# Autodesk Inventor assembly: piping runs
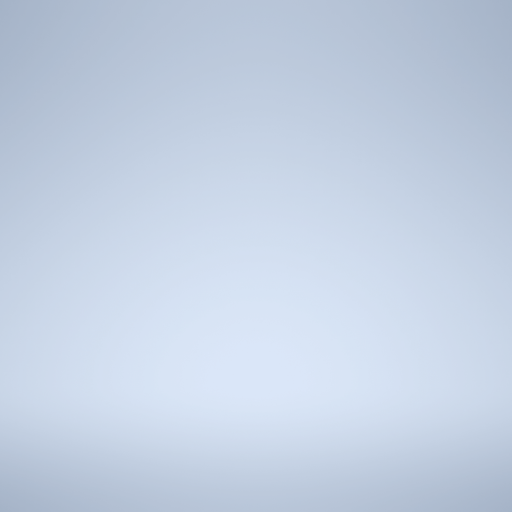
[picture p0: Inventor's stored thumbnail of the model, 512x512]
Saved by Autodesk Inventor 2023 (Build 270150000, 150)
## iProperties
ActiveState: False
Angle: UnInitValue
BendRadius: 12.700 mm
CouplingKey: UnInitValue
DefaultBendRadius: UnInitValue
Diameter: 1/2
DiameterType: Nominal
Elbow45Key: UnInitValue
Elbow90Key: UnInitValue
ElbowCustomKey: UnInitValue
Ending: UnInitValue
FittingMaterial: UnInitValue
FittingStandard: UnInitValue
FlangeKey: UnInitValue
Gap: UnInitValue
GasketKey: UnInitValue
ID: 12.700 mm
IsButtWelded: UnInitValue
IsFlanged: UnInitValue
IsSelfDraining: UnInitValue
Material: UnInitValue
MixedUnits: UnInitValue
Name: Przewód hydrauliczny – bez złączek
OD: 22.352 mm
PipeKey: v3#d489867e-ac9b-47ea-b952-0a1b885f66be#4
PipeType: Flexible Hose
PipingComponentColor: Jak materiał
RoundUpValue: 3.175 mm
RouteDirection45: UnInitValue
RouteDirection90: UnInitValue
Schedule: ID=0.5
ShowGap: UnInitValue
Standard: UnInitValue
SuppressEndFitting: True
SuppressStartFitting: True
UseFlangsForCouplings: UnInitValue
UseSubASM: True
_ComponentInfo: <CS><C N="Pipe" R="1.117600" OR="1.117600" IR="0.635000" PL="PL" PartType="" SymKey="" PN="Parker Hydraulic Hose - No Skive 1/2"><CO N="1"><FE V="0"/><FD V="0"/
BendRadius: UnInitValue
CategoryName: UnInitValue
CouplingKey: v3#12b64993-10e6-4915-8315-0c0cce209ad0#8
Diameter: M40
Elbow45Key: v3#28e76e79-e22c-40ab-8be2-ff545b1407c5#8
Elbow90Key: v3#1f65ece3-c41a-48d4-8661-909ed34ade86#8
EndFittingKey: UnInitValue
IntermediateSegmentsInc: 1.000 mm
IntermediateSegmentsMax: 5000.000 mm
IntermediateSegmentsMin: 60.000 mm
Name: JIS G 3458/JIS B 2316 - Rury stalowe spawane i łączniki
PipeKey: v3#da14b0ab-0b36-4851-8d66-8c9cd0bcbe86#23
PipeType: Rigid Pipe
RoundUpValue: UnInitValue
RouteDirection45: True
RouteDirection90: True
Schedule: 80
StartFittingKey: UnInitValue
SuppressEndFitting: UnInitValue
SuppressStartFitting: UnInitValue
TerminationSegmentsInc: 1.000 mm
TerminationSegmentsMax: 5000.000 mm
TerminationSegmentsMin: 60.000 mm
UseSubASM: UnInitValue
_ComponentInfo: <CS><C N="Pipe" R="2.430000" IR="1.920000" PL="PL" PN="JIS G 3458 Pipe 40 A x Sch 80"><CO N="1"><FE V="0"/><FD V="1"/><ET V="Welded"/><NS  V="M40"/><MA V="0.000
CouplingKey: v3#ed415c76-4cec-44a3-ba67-72e47bf70384#4
Elbow45Key: v3#2e5fd082-3851-4eb0-bde1-6c7078a7d72b#4
Elbow90Key: v3#82a08401-12d7-413b-b7f9-9cf3b607be7b#4
IntermediateSegmentsInc: 2.540 mm
IntermediateSegmentsMax: 5080.000 mm
IntermediateSegmentsMin: 25.400 mm
Name: ASTM A53/A53M-ASME B16.11 - Rury stalowe spawane
PipeKey: v3#4ce5e9fa-6da0-4801-ac02-ee7a0fb518d6#7
Schedule: 40
TerminationSegmentsInc: 2.540 mm
TerminationSegmentsMax: 5080.000 mm
TerminationSegmentsMin: 25.400 mm
_ComponentInfo: <CS><C N="Pipe" R="1.066800" IR="0.789940" PL="PL" PN="ASTM A 53/A 53M Pipe 1/2 - Schedule 40"><CO N="1"><FE V="0"/><FD V="0"/><ET V="Welded"/><NS  V="1/2"/><MA
CouplingKey: v3#7e56b2cb-a132-4546-b8a7-a14538454b94#3
Elbow45Key: v3#a96c5204-26e4-4bb2-b8f1-f0623fbc94bb#2
Elbow90Key: v3#b72bb08b-ad33-47cc-a03d-7f3d76c6616b#3
ID: UnInitValue
IntermediateSegmentsMin: 50.800 mm
IsButtWelded: False
IsFlanged: False
IsSelfDraining: False
MixedUnits: False
Name: ISO 7598/ISO 49 - Rury stalowe gwintowane ze stalowymi łącznikami
OD: UnInitValue
PipeKey: v3#1052637f-74b5-47f4-adeb-d4e8d3fa53b8#1
Schedule: ID=16.1
TerminationSegmentsMin: 50.800 mm
_ComponentInfo: <CS><C N="Pipe" R="1.065000" IR="0.805000" PL="PL" PN="ISO 7598 Tube with Threaded Ends DN15"><CO N="1"><FE V="0"/><FD V="1"/><ET V="Threaded"/><NS V="1/2"/><MA
EndFittingKey: v3#c5e461f5-5e73-4f2e-8c1e-4358d4d6f46c#4
Name: Przewód hydrauliczny – gwint wewnętrzny - obrotowy
StartFittingKey: v3#c5e461f5-5e73-4f2e-8c1e-4358d4d6f46c#4
SuppressEndFitting: False
SuppressStartFitting: False
Diameter: 6
Elbow90Key: v3#97ecdcaf-8aa3-4fb0-8b6a-3da783de2ad5#108
Gap: 1.575 mm
IntermediateSegmentsInc: 0.000 mm
IntermediateSegmentsMin: 76.200 mm
IsButtWelded: True
Name: ASTM A 53/A-ASME B16.9 - Rura stalowa ze szwem
PipeKey: v3#4ce5e9fa-6da0-4801-ac02-ee7a0fb518d6#77
RouteDirection45: False
ShowGap: True
TerminationSegmentsInc: 0.000 mm
TerminationSegmentsMin: 76.200 mm
_ComponentInfo: <CS><C N="Elbow90" ER="15.240000" S1="15.240000" S2="15.240000" D1="0.000000" D2="0.000000" PartType="fitting" SymKey="ELBW"><CO N="1"><FE V="2"/><FD V="0"/><ET
CouplingKey: v3#181262db-c004-4877-bc40-c64b931a44f6#3
Elbow45Key: v3#960407aa-00b9-4d72-aae7-d50595845cfd#3
Elbow90Key: v3#6c92b367-65e9-486b-b952-db434ae2548d#3
IntermediateSegmentsMin: 20.000 mm
Name: JIS G 3442/JIS B 2301  Rury stalowe gwintowane ze stalowymi łącznikami
PipeKey: v3#9964fba4-9d5a-4d75-85a8-e38022ccdce1#2
TerminationSegmentsMin: 20.000 mm
_ComponentInfo: <CS><C N="Pipe" R="1.085000" IR="0.805000" PL="PL" PN="JIS G 3442 Pipe with Threaded Ends 21.7 x 2.8"><CO N="1"><FE V="0"/><FD V="1"/><ET V="Threaded"/><NS V="1
CouplingKey: v3#771d4942-b9e7-43bc-9d41-ab12a9580492#3
Elbow45Key: v3#626cc28c-1a24-4045-be0d-40d896dc828d#3
Elbow90Key: v3#bc6b44ab-9235-4590-b699-74498030a1ff#3
Name: ANSI/ASME B36.19M-ASME B16.3 - Rury gwintowane ze stalowymi łącznikami
PipeKey: v3#323c0148-c750-449d-a0c6-11721f2a5046#1
Schedule: 40S
_ComponentInfo: <CS><C N="Pipe" R="1.066800" IR="0.789940" PL="PL" PN="ANSI/ASME B36.19M Pipe with Threaded Ends 1/2 - Schedule 40S"><CO N="1"><FE V="0"/><FD  V="1"/><ET V="Thr
Elbow45Key: v3#97879d80-057e-491b-840b-74a9b3a7cf63#17
Elbow90Key: v3#ace818b0-7b7c-4ad9-b19c-6da358a202c1#17
Name: DIN 2458/DIN 2605 - Rury stalowe spawane i łączniki
PipeKey: v3#dcef2839-8903-4c98-a96c-b861f5d9bb7f#98
Schedule: ID=30.7
_ComponentInfo: <CS><C N="Pipe" R="2.415000" IR="1.535000" PL="PL" PN="DIN 2458 Pipe 48.3 x 8.8"><CO N="1"><FE V="2"/><FD V="0"/><ET V="Welded"/><NS V="M40"/><MA  V="0.000000"/
EndFittingKey: v3#c8250148-a7b6-458b-b7bd-3b56763ca7cc#13
Name: Przewód hydrauliczny – gwint stożkowy zewnętrzny
StartFittingKey: v3#c8250148-a7b6-458b-b7bd-3b56763ca7cc#13
Elbow90Key: v3#6a678020-d9d9-4685-bba9-906b9a167083#10
FlangeKey: v3#c11442d2-c568-438f-a870-8ac9b5b636cb#10
GasketKey: v3#2a41914c-f5fb-4682-9c6a-1870d826d3d0#23
IsFlanged: True
Name: ASTM A 53/A-ASME B16.5 - Rura stalowa gwintowana kołnierzowa
PipeKey: v3#c5bd7d28-cdb3-4507-9f3d-c2787d93fe8a#40
_ComponentInfo: <CS><C N="Elbow90" ER="21.590000" S1="21.590000" S2="21.590000" D1="0.000000" D2="0.000000" PartType="fitting" SymKey="ELFL"><CO N="1"><FE V="2"/><FD V="1"/><ET
CouplingKey: v3#d2599e7a-1865-48da-a234-5418a1cd5dfe#3
Elbow45Key: v3#6ce5b1be-37aa-4928-b23a-0df64e6ddf38#2
Elbow90Key: v3#9fba244e-81ed-4fc6-a9ac-7eb372fa3ffe#3
Name: DIN 2458/DIN EN 10242 - Rury stalowe gwintowane i stalowe łączniki
PipeKey: v3#d689fd5f-ac5a-46d7-a883-3089b2f6e0a4#28
Schedule: ID=12.3
_ComponentInfo: <CS><C N="Pipe" R="1.065000" IR="0.615000" PL="PL" PN="DIN 2458 Pipe with Threaded Ends 21.3 x 4.5"><CO N="1"><FE V="0"/><FD V="1"/><ET V="Threaded"/><NS V="1/2
CouplingKey: v3#b06656e5-2b55-488c-bcf0-6a90c79c4683#2
Elbow45Key: v3#421a8b99-1721-409a-bc3b-c00889561754#1
Elbow90Key: v3#17490b17-1dd8-40fc-8de7-1a70c3bab2d7#1
IntermediateSegmentsMax: 2540.000 mm
Name: ISO 4065-ISO 3633 - Rury i złączki PCV
PipeKey: v3#4f84f716-5ba0-45ef-967a-c32c3d7345ce#70
Schedule: S40
TerminationSegmentsMax: 2540.000 mm
_ComponentInfo: <CS><C N="Pipe" R="2.000000" IR="1.950000" PL="PL" PN="ISO 4065 Pipe 40 x 0.5 S40"><CO N="1"><FE V="0"/><FD V="0"/><ET V="Jointed"/><NS V="M40"/><MA  V="6.00000
CouplingKey: v3#0dc1ae02-7bbf-4ccf-8498-581434b0a765#3
DefaultBendRadius: 50.800 mm
IntermediateSegmentsMin: 0.000 mm
Name: ASTM B 88-ASME B16.22 - Rury miedziane lutowane
PipeKey: v3#44b182c9-4bce-4825-bb4d-596143122252#7
PipeType: Tubing
Schedule: L
TerminationSegmentsMin: 0.000 mm
_ComponentInfo: <CS><C N="Pipe" R="0.793750" IR="0.692150" PL="PL" PN="ASTM B 88 Tube 1/2 - Type L"><CO N="1"><FE V="0"/><FD V="0"/><ET V="Soldered"/><NS V="1/2"/><MA V="2.5400
Created: 2006-09
Part Number: piping runs
Document SubType Name: Tube & Pipe
Manufacturer: Standard
Standards Organization: Custom
FlangeKey: v3#24991861-26e3-4c21-a713-f46e314eddd5#10
Gap: 2.388 mm
Name: ASTM A 53/A 53M - Rura stalowa kołnierzowa/spawana doczołowo
UseFlangsForCouplings: False
_ComponentInfo: <CS><C N="Pipe" R="8.413750" OR="8.413750" IR="7.702550" PL="PL" PartType="pipe" SymKey="" PN="ASTM A 53/A 53M Pipe 6 - Schedule 40"><CO N="1"><FE V="2"/><FD V=
ActiveState: True
CouplingKey: v3#52ad3977-2b89-4007-a6a6-7626bac0ae85#4
Elbow45Key: v3#5c2ab816-abcb-49a6-a106-4733af000f51#4
Elbow90Key: v3#160eac10-3e6f-4b5c-839c-61eee0d373dc#4
ID: 16.510 mm
Name: ASME B36.10M-ASME B16.11 - Rury stalowe gwintowane
OD: 21.336 mm
PipeKey: v3#4a736116-503a-44ad-a922-868ac6b46736#1
Schedule: 30
_ComponentInfo: <CS><C N="Pipe" R="1.066800" IR="0.825500" PL="PL" PN="ASME B36.10M Pipe with Threaded Ends 1/2 - Schedule 30"><CO N="1"><FE V="0"/><FD V="1"/><ET  V="Threaded"
Angle: 92.00 deg
Diameter: 1
Elbow45Key: v3#bf26aa2a-f3dd-474c-8758-922a145c2b02#15
Elbow90Key: v3#3e93288f-9bb7-4e46-9d6b-544f8c20ca1c#3
ElbowCustomKey: v3#1f3bd44a-47ab-42f9-b3e0-74afa0c3f0ca#3
IsSelfDraining: True
Name: ASME BPE - Rura stalowa kołnierzowa
PipeKey: v3#b10c956f-6fc6-429e-8056-0864a8581764#35
Schedule: ID=0.87
_ComponentInfo: <CS><C N="Pipe" R="1.270000" OR="1.270000" IR="1.104900" PL="PL" PartType="pipe" SymKey="" PN="ASTM A 269 Tube with Welded ends 1 x 0.87"><CO N="1"><FE V="2"/><
EndFittingKey: v3#b50cb43e-68c0-48ac-8e25-7ef224ce0e6c#3
Name: Przewód hydrauliczny – gwint zewnętrzny prosty
StartFittingKey: v3#b50cb43e-68c0-48ac-8e25-7ef224ce0e6c#3
CouplingKey: v3#3edf83e2-464b-4b31-84c5-c329ffbf2a4f#5
Elbow45Key: v3#2f597a97-b15b-49d4-87cb-7bfe69eb62ee#5
Elbow90Key: v3#fbd68fd5-590c-4cb5-8c20-9e9bdd396a04#5
Name: DIN 8062/DIN 8063 - Rury i złączki PCV-U
PipeKey: v3#3d294dc7-89c3-4c37-a0ae-28c15a73bfd0#13
Schedule: 6.3
_ComponentInfo: <CS><C N="Pipe" R="2.000000" IR="1.700000" PL="PL" PN="DIN 8062 Pipe 40 x 3"><CO N="1"><FE V="0"/><FD V="0"/><ET V="Jointed"/><NS V="M40"/><MA  V="8.000000"/><M
CouplingKey: v3#eaa8de87-dc67-4eca-ba7e-4267a30f8f7f#2
Elbow45Key: v3#2769403e-a4fd-4a4c-8e4c-659ea845bd78#2
Elbow90Key: v3#c4513a61-3106-4a78-baf9-a1badd100245#2
IntermediateSegmentsMax: 2500.000 mm
Name: JIS K 6741/JIS K 6739 - Rury i złączki PCV-U
PipeKey: v3#45338dd0-af69-48c0-a2ed-8ade33a08701#5
Schedule: VP
TerminationSegmentsMax: 2500.000 mm
_ComponentInfo: <CS><C N="Pipe" R="2.400000" IR="2.040000" PL="PL" PN="JIS K 6741 Pipe VP 40"><CO N="1"><FE V="0"/><FD V="1"/><ET V="Jointed"/><NS V="M40"/><MA  V="4.000000"/><
CouplingKey: v3#29993622-4c6a-437e-8b8c-43a0846f8735#1
Elbow45Key: v3#d7b5d569-4a12-4d65-ba55-12203d6ac7ed#1
Elbow90Key: v3#25d2a8db-6517-4627-a5a4-9d27e4d26b9b#1
Name: ASTM D 1785-ASTM D 2466 - Rury i złączki PCV
PipeKey: v3#4bf12049-4375-491b-8f13-d4ee0c517c57#1
_ComponentInfo: <CS><C N="Pipe" R="1.066800" IR="0.789940" PL="PL" PN="ASTM D 1785 Pipe 1/2 - Schedule 40"><CO N="1"><FE V="0"/><FD V="0"/><ET V="Jointed"/><NS  V="1/2"/><MA V=
EndFittingKey: v3#cc3bd835-95a2-497d-9893-176cd9c426f6#7
Name: Przewód hydrauliczny – gwint stożkowy wewnętrzny
StartFittingKey: v3#cc3bd835-95a2-497d-9893-176cd9c426f6#7
EndFittingKey: v3#933069c9-73b6-4141-af99-628d4a97b2c2#1
Name: Przewód hydrauliczny – złączki kołnierzowe SAE
StartFittingKey: v3#933069c9-73b6-4141-af99-628d4a97b2c2#1
count: 54
Refkey_Axis1_Context: 2|0|0|0|1|0|0|0|
Refkey_Axis1: 6|0|0|0|44|0|0|0|78|0|65|0|77|0|69|0|83|0|10|0|67|0|111|0|108|0|111|0|114|0|115|0|10|0|49|0|58|0|10|0|10|0|69|0|78|0|68|0|10|0|0|0|
Refkey_Axis2_Context: 2|0|0|0|1|0|0|0|
Refkey_Axis2: 6|0|0|0|88|0|0|0|78|0|65|0|77|0|69|0|83|0|10|0|67|0|111|0|108|0|111|0|114|0|115|0|10|0|49|0|58|0|82|0|111|0|117|0|116|0|101|0|32|0|85|0|73|0|32|0|84|0|111|0|111
Refkey_Axis3_Context: 2|0|0|0|1|0|0|0|
Refkey_Axis3: 6|0|0|0|88|0|0|0|78|0|65|0|77|0|69|0|83|0|10|0|67|0|111|0|108|0|111|0|114|0|115|0|10|0|49|0|58|0|82|0|111|0|117|0|116|0|101|0|32|0|85|0|73|0|32|0|84|0|111|0|111
Refkey_Ext_Context: 2|0|0|0|1|0|0|0|
Refkey_Ext: 6|0|0|0|92|0|0|0|78|0|65|0|77|0|69|0|83|0|10|0|67|0|111|0|108|0|111|0|114|0|115|0|10|0|49|0|58|0|82|0|111|0|117|0|116|0|101|0|32|0|85|0|73|0|32|0|84|0|111|0|111
Refkey_Snap_Context: 2|0|0|0|1|0|0|0|
Refkey_Snap: 6|0|0|0|84|0|0|0|78|0|65|0|77|0|69|0|83|0|10|0|67|0|111|0|108|0|111|0|114|0|115|0|10|0|49|0|58|0|82|0|111|0|117|0|116|0|101|0|32|0|85|0|73|0|32|0|84|0|111|0|111
Elbow45Key: v3#81684a3f-f2a4-4fe6-95b1-f067ddead22f#1
Elbow90Key: v3#451ae64e-c79d-4cba-b533-c09b8090ecb2#1
IntermediateSegmentsInc: 10.000 mm
IntermediateSegmentsMax: 9000.000 mm
IntermediateSegmentsMin: 1000.000 mm
Name: ISO 2531 - Rury żelazne kołnierzowe i łączniki
PipeKey: v3#f52fbdcb-ece8-4303-8b76-5dbe8c7f2f9c#16
Schedule: PN10
TerminationSegmentsInc: 10.000 mm
TerminationSegmentsMax: 9000.000 mm
TerminationSegmentsMin: 1000.000 mm
_ComponentInfo: <CS><C N="Pipe" R="2.700000" IR="2.000000" PL="PL" PN="ISO 2531 Pipe with Integrally Cast Flanges DN40 PN 10"><CO N="1"><FE V="0"/><FD V="0"/><ET  V="Flanged"/>
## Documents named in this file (1)
- C:\Users\CHS\Desktop\2023_plk\piping runs.iam
